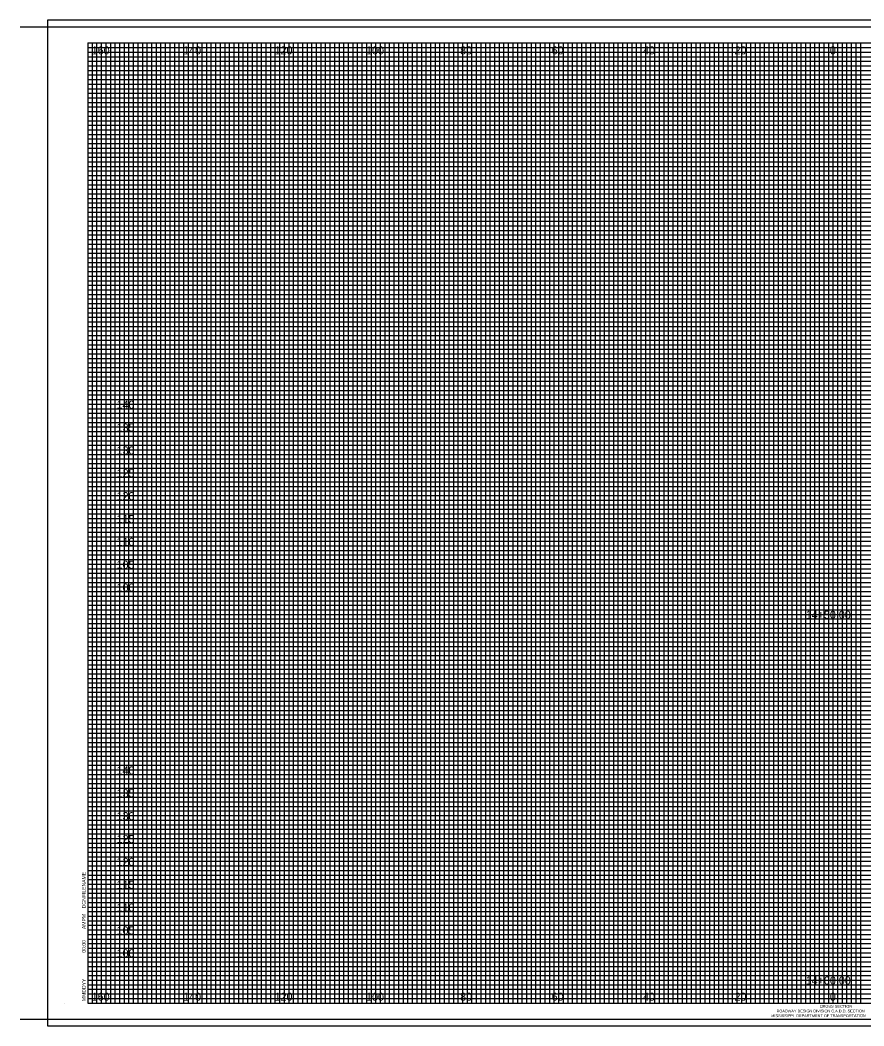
# Model space of a CAD drawing. Extents: x 21281 to 21817, y 6470 to 8300.
# Drawn here: x 21465 to 21649.5, y 7389.8 to 7609.8 of the extents above; entities that cross this region are included whole.
import ezdxf

# ---------------------------------------------------------------- set-up
doc = ezdxf.new("R2010")
doc.units = 0
for name, color, linetype in [('SHEET_BORDER', 7, 'Continuous'), ('SHEET_BORDER_TX', 7, 'Continuous'), ('SHEET_DATE_DGN_TX', 7, 'Continuous'), ('SHEET_PLOTTING_SHAPE', 7, 'Continuous'), ('XS_SHEET_LABELS_ELEVATION', 7, 'Continuous'), ('XS_SHEET_LABELS_OFFSET', 7, 'Continuous'), ('XS_SHEET_LABELS_STATION', 7, 'Continuous'), ('XS_SHEET_MAJOR_GRIDS', 7, 'Continuous'), ('XS_SHEET_MEDIUM_GRIDS', 7, 'Continuous'), ('XS_SHEET_MINOR_GRIDS', 7, 'Continuous')]:
    doc.layers.add(name, color=color, linetype=linetype)

msp = doc.modelspace()

# ---------------------------------------------------------------- linework, layer by layer
at = {"layer": 'SHEET_BORDER'}
for p, q in [((21465.04, 7608.34), (21817.04, 7608.34)), ((21479.84, 7604.84), (21814.84, 7604.84)), ((21479.84, 7604.84), (21479.84, 7394.84)), ((21623.84, 7394.84), (21623.84, 7604.84)), ((21474.84, 7394.84), (21474.84, 7394.84)), ((21479.84, 7394.84), (21814.84, 7394.84)), ((21465.04, 7391.34), (21817.04, 7391.34))]:
    msp.add_line(p, q, dxfattribs=at)
at = {"layer": 'SHEET_PLOTTING_SHAPE'}
msp.add_lwpolyline([(21471.04, 7389.84), (21817.04, 7389.84), (21817.04, 7609.84), (21471.04, 7609.84)], close=True, dxfattribs=at)
at = {"layer": 'XS_SHEET_MAJOR_GRIDS'}
for p, q in [((21484.84, 7394.84), (21484.84, 7604.84)), ((21494.84, 7394.84), (21494.84, 7604.84)), ((21504.84, 7394.84), (21504.84, 7604.84)), ((21514.84, 7394.84), (21514.84, 7604.84)), ((21524.84, 7394.84), (21524.84, 7604.84)), ((21534.84, 7394.84), (21534.84, 7604.84)), ((21544.84, 7394.84), (21544.84, 7604.84)), ((21554.84, 7394.84), (21554.84, 7604.84)), ((21564.84, 7394.84), (21564.84, 7604.84)), ((21574.84, 7394.84), (21574.84, 7604.84)), ((21584.84, 7394.84), (21584.84, 7604.84)), ((21594.84, 7394.84), (21594.84, 7604.84)), ((21604.84, 7394.84), (21604.84, 7604.84)), ((21614.84, 7394.84), (21614.84, 7604.84)), ((21624.84, 7394.84), (21624.84, 7604.84)), ((21634.84, 7394.84), (21634.84, 7604.84)), ((21644.84, 7394.84), (21644.84, 7604.84)), ((21479.84, 7594.84), (21814.84, 7594.84)), ((21479.84, 7584.84), (21814.84, 7584.84)), ((21479.84, 7574.84), (21814.84, 7574.84)), ((21479.84, 7564.84), (21814.84, 7564.84)), ((21479.84, 7554.84), (21814.84, 7554.84)), ((21479.84, 7544.84), (21814.84, 7544.84)), ((21479.84, 7534.84), (21814.84, 7534.84)), ((21479.84, 7524.84), (21814.84, 7524.84)), ((21479.84, 7514.84), (21814.84, 7514.84)), ((21479.84, 7504.84), (21814.84, 7504.84)), ((21479.84, 7494.84), (21814.84, 7494.84)), ((21479.84, 7484.84), (21814.84, 7484.84)), ((21479.84, 7474.84), (21814.84, 7474.84)), ((21479.84, 7464.84), (21814.84, 7464.84)), ((21479.84, 7454.84), (21814.84, 7454.84)), ((21479.84, 7444.84), (21814.84, 7444.84)), ((21479.84, 7434.84), (21814.84, 7434.84)), ((21479.84, 7424.84), (21814.84, 7424.84)), ((21479.84, 7414.84), (21814.84, 7414.84)), ((21479.84, 7404.84), (21814.84, 7404.84))]:
    msp.add_line(p, q, dxfattribs=at)
at = {"layer": 'XS_SHEET_MEDIUM_GRIDS'}
for p, q in [((21489.84, 7394.84), (21489.84, 7604.84)), ((21499.84, 7394.84), (21499.84, 7604.84)), ((21509.84, 7394.84), (21509.84, 7604.84)), ((21519.84, 7394.84), (21519.84, 7604.84)), ((21529.84, 7394.84), (21529.84, 7604.84)), ((21539.84, 7394.84), (21539.84, 7604.84)), ((21549.84, 7394.84), (21549.84, 7604.84)), ((21559.84, 7394.84), (21559.84, 7604.84)), ((21569.84, 7394.84), (21569.84, 7604.84)), ((21579.84, 7394.84), (21579.84, 7604.84)), ((21589.84, 7394.84), (21589.84, 7604.84)), ((21599.84, 7394.84), (21599.84, 7604.84)), ((21609.84, 7394.84), (21609.84, 7604.84)), ((21619.84, 7394.84), (21619.84, 7604.84)), ((21629.84, 7394.84), (21629.84, 7604.84)), ((21639.84, 7394.84), (21639.84, 7604.84)), ((21479.84, 7599.84), (21787.84, 7599.84)), ((21479.84, 7589.84), (21814.84, 7589.84)), ((21479.84, 7579.84), (21814.84, 7579.84)), ((21479.84, 7569.84), (21814.84, 7569.84)), ((21479.84, 7559.84), (21814.84, 7559.84)), ((21479.84, 7549.84), (21814.84, 7549.84)), ((21479.84, 7539.84), (21814.84, 7539.84)), ((21479.84, 7529.84), (21814.84, 7529.84)), ((21479.84, 7519.84), (21814.84, 7519.84)), ((21479.84, 7509.84), (21814.84, 7509.84)), ((21479.84, 7499.84), (21814.84, 7499.84)), ((21479.84, 7489.84), (21814.84, 7489.84)), ((21479.84, 7479.84), (21814.84, 7479.84)), ((21479.84, 7469.84), (21814.84, 7469.84)), ((21479.84, 7459.84), (21814.84, 7459.84)), ((21479.84, 7449.84), (21814.84, 7449.84)), ((21479.84, 7439.84), (21814.84, 7439.84)), ((21479.84, 7429.84), (21814.84, 7429.84)), ((21479.84, 7419.84), (21814.84, 7419.84)), ((21479.84, 7409.84), (21814.84, 7409.84)), ((21479.84, 7399.84), (21804.84, 7399.84))]:
    msp.add_line(p, q, dxfattribs=at)
at = {"layer": 'XS_SHEET_MINOR_GRIDS'}
for p, q in [((21479.84, 7603.84), (21787.84, 7603.84)), ((21480.84, 7394.84), (21480.84, 7604.84)), ((21481.84, 7394.84), (21481.84, 7604.84)), ((21482.84, 7394.84), (21482.84, 7604.84)), ((21483.84, 7394.84), (21483.84, 7604.84)), ((21485.84, 7394.84), (21485.84, 7604.84)), ((21486.84, 7394.84), (21486.84, 7604.84)), ((21487.84, 7394.84), (21487.84, 7604.84)), ((21488.84, 7394.84), (21488.84, 7604.84)), ((21490.84, 7394.84), (21490.84, 7604.84)), ((21491.84, 7394.84), (21491.84, 7604.84)), ((21492.84, 7394.84), (21492.84, 7604.84)), ((21493.84, 7394.84), (21493.84, 7604.84)), ((21495.84, 7394.84), (21495.84, 7604.84)), ((21496.84, 7394.84), (21496.84, 7604.84)), ((21497.84, 7394.84), (21497.84, 7604.84)), ((21498.84, 7394.84), (21498.84, 7604.84)), ((21500.84, 7394.84), (21500.84, 7604.84)), ((21501.84, 7394.84), (21501.84, 7604.84)), ((21502.84, 7394.84), (21502.84, 7604.84)), ((21503.84, 7394.84), (21503.84, 7604.84)), ((21505.84, 7394.84), (21505.84, 7604.84)), ((21506.84, 7394.84), (21506.84, 7604.84)), ((21507.84, 7394.84), (21507.84, 7604.84)), ((21508.84, 7394.84), (21508.84, 7604.84)), ((21510.84, 7394.84), (21510.84, 7604.84)), ((21511.84, 7394.84), (21511.84, 7604.84)), ((21512.84, 7394.84), (21512.84, 7604.84)), ((21513.84, 7394.84), (21513.84, 7604.84)), ((21515.84, 7394.84), (21515.84, 7604.84)), ((21516.84, 7394.84), (21516.84, 7604.84)), ((21517.84, 7394.84), (21517.84, 7604.84)), ((21518.84, 7394.84), (21518.84, 7604.84)), ((21520.84, 7394.84), (21520.84, 7604.84)), ((21521.84, 7394.84), (21521.84, 7604.84)), ((21522.84, 7394.84), (21522.84, 7604.84)), ((21523.84, 7394.84), (21523.84, 7604.84)), ((21525.84, 7394.84), (21525.84, 7604.84)), ((21526.84, 7394.84), (21526.84, 7604.84)), ((21527.84, 7394.84), (21527.84, 7604.84)), ((21528.84, 7394.84), (21528.84, 7604.84)), ((21530.84, 7394.84), (21530.84, 7604.84)), ((21531.84, 7394.84), (21531.84, 7604.84)), ((21532.84, 7394.84), (21532.84, 7604.84)), ((21533.84, 7394.84), (21533.84, 7604.84)), ((21535.84, 7394.84), (21535.84, 7604.84)), ((21536.84, 7394.84), (21536.84, 7604.84)), ((21537.84, 7394.84), (21537.84, 7604.84)), ((21538.84, 7394.84), (21538.84, 7604.84)), ((21540.84, 7394.84), (21540.84, 7604.84)), ((21541.84, 7394.84), (21541.84, 7604.84)), ((21542.84, 7394.84), (21542.84, 7604.84)), ((21543.84, 7394.84), (21543.84, 7604.84)), ((21545.84, 7394.84), (21545.84, 7604.84)), ((21546.84, 7394.84), (21546.84, 7604.84)), ((21547.84, 7394.84), (21547.84, 7604.84)), ((21548.84, 7394.84), (21548.84, 7604.84)), ((21550.84, 7394.84), (21550.84, 7604.84)), ((21551.84, 7394.84), (21551.84, 7604.84)), ((21552.84, 7394.84), (21552.84, 7604.84)), ((21553.84, 7394.84), (21553.84, 7604.84)), ((21555.84, 7394.84), (21555.84, 7604.84)), ((21556.84, 7394.84), (21556.84, 7604.84)), ((21557.84, 7394.84), (21557.84, 7604.84)), ((21558.84, 7394.84), (21558.84, 7604.84)), ((21560.84, 7394.84), (21560.84, 7604.84)), ((21561.84, 7394.84), (21561.84, 7604.84)), ((21562.84, 7394.84), (21562.84, 7604.84)), ((21563.84, 7394.84), (21563.84, 7604.84)), ((21565.84, 7394.84), (21565.84, 7604.84)), ((21566.84, 7394.84), (21566.84, 7604.84)), ((21567.84, 7394.84), (21567.84, 7604.84)), ((21568.84, 7394.84), (21568.84, 7604.84)), ((21570.84, 7394.84), (21570.84, 7604.84)), ((21571.84, 7394.84), (21571.84, 7604.84)), ((21572.84, 7394.84), (21572.84, 7604.84)), ((21573.84, 7394.84), (21573.84, 7604.84)), ((21575.84, 7394.84), (21575.84, 7604.84)), ((21576.84, 7394.84), (21576.84, 7604.84)), ((21577.84, 7394.84), (21577.84, 7604.84)), ((21578.84, 7394.84), (21578.84, 7604.84)), ((21580.84, 7394.84), (21580.84, 7604.84)), ((21581.84, 7394.84), (21581.84, 7604.84)), ((21582.84, 7394.84), (21582.84, 7604.84)), ((21583.84, 7394.84), (21583.84, 7604.84)), ((21585.84, 7394.84), (21585.84, 7604.84)), ((21586.84, 7394.84), (21586.84, 7604.84)), ((21587.84, 7394.84), (21587.84, 7604.84)), ((21588.84, 7394.84), (21588.84, 7604.84)), ((21590.84, 7394.84), (21590.84, 7604.84)), ((21591.84, 7394.84), (21591.84, 7604.84)), ((21592.84, 7394.84), (21592.84, 7604.84)), ((21593.84, 7394.84), (21593.84, 7604.84)), ((21595.84, 7394.84), (21595.84, 7604.84)), ((21596.84, 7394.84), (21596.84, 7604.84)), ((21597.84, 7394.84), (21597.84, 7604.84)), ((21598.84, 7394.84), (21598.84, 7604.84)), ((21600.84, 7394.84), (21600.84, 7604.84)), ((21601.84, 7394.84), (21601.84, 7604.84)), ((21602.84, 7394.84), (21602.84, 7604.84)), ((21603.84, 7394.84), (21603.84, 7604.84)), ((21605.84, 7394.84), (21605.84, 7604.84)), ((21606.84, 7394.84), (21606.84, 7604.84)), ((21607.84, 7394.84), (21607.84, 7604.84)), ((21608.84, 7394.84), (21608.84, 7604.84)), ((21610.84, 7394.84), (21610.84, 7604.84)), ((21611.84, 7394.84), (21611.84, 7604.84)), ((21612.84, 7394.84), (21612.84, 7604.84)), ((21613.84, 7394.84), (21613.84, 7604.84)), ((21615.84, 7394.84), (21615.84, 7604.84)), ((21616.84, 7394.84), (21616.84, 7604.84)), ((21617.84, 7394.84), (21617.84, 7604.84)), ((21618.84, 7394.84), (21618.84, 7604.84)), ((21620.84, 7394.84), (21620.84, 7604.84)), ((21621.84, 7394.84), (21621.84, 7604.84)), ((21622.84, 7394.84), (21622.84, 7604.84)), ((21625.84, 7394.84), (21625.84, 7604.84)), ((21626.84, 7394.84), (21626.84, 7604.84)), ((21627.84, 7394.84), (21627.84, 7604.84)), ((21628.84, 7394.84), (21628.84, 7604.84)), ((21630.84, 7394.84), (21630.84, 7604.84)), ((21631.84, 7394.84), (21631.84, 7604.84)), ((21632.84, 7394.84), (21632.84, 7604.84)), ((21633.84, 7394.84), (21633.84, 7604.84)), ((21635.84, 7394.84), (21635.84, 7604.84)), ((21636.84, 7394.84), (21636.84, 7604.84)), ((21637.84, 7394.84), (21637.84, 7604.84)), ((21638.84, 7394.84), (21638.84, 7604.84)), ((21640.84, 7394.84), (21640.84, 7604.84)), ((21641.84, 7394.84), (21641.84, 7604.84)), ((21642.84, 7394.84), (21642.84, 7604.84)), ((21643.84, 7394.84), (21643.84, 7604.84)), ((21645.84, 7394.84), (21645.84, 7604.84)), ((21646.84, 7394.84), (21646.84, 7604.84)), ((21647.84, 7394.84), (21647.84, 7604.84)), ((21648.84, 7394.84), (21648.84, 7604.84)), ((21479.84, 7602.84), (21787.84, 7602.84)), ((21479.84, 7601.84), (21787.84, 7601.84)), ((21479.84, 7600.84), (21787.84, 7600.84)), ((21479.84, 7598.84), (21787.84, 7598.84)), ((21479.84, 7597.84), (21787.84, 7597.84)), ((21479.84, 7596.84), (21787.84, 7596.84)), ((21479.84, 7595.84), (21814.84, 7595.84)), ((21479.84, 7593.84), (21814.84, 7593.84)), ((21479.84, 7592.84), (21814.84, 7592.84)), ((21479.84, 7591.84), (21814.84, 7591.84)), ((21479.84, 7590.84), (21814.84, 7590.84)), ((21479.84, 7588.84), (21814.84, 7588.84)), ((21479.84, 7587.84), (21814.84, 7587.84)), ((21479.84, 7586.84), (21814.84, 7586.84)), ((21479.84, 7585.84), (21814.84, 7585.84)), ((21479.84, 7583.84), (21814.84, 7583.84)), ((21479.84, 7582.84), (21814.84, 7582.84)), ((21479.84, 7581.84), (21814.84, 7581.84)), ((21479.84, 7580.84), (21814.84, 7580.84)), ((21479.84, 7578.84), (21814.84, 7578.84)), ((21479.84, 7577.84), (21814.84, 7577.84)), ((21479.84, 7576.84), (21814.84, 7576.84)), ((21479.84, 7575.84), (21814.84, 7575.84)), ((21479.84, 7573.84), (21814.84, 7573.84)), ((21479.84, 7572.84), (21814.84, 7572.84)), ((21479.84, 7571.84), (21814.84, 7571.84)), ((21479.84, 7570.84), (21814.84, 7570.84)), ((21479.84, 7568.84), (21814.84, 7568.84)), ((21479.84, 7567.84), (21814.84, 7567.84)), ((21479.84, 7566.84), (21814.84, 7566.84)), ((21479.84, 7565.84), (21814.84, 7565.84)), ((21479.84, 7563.84), (21814.84, 7563.84)), ((21479.84, 7562.84), (21814.84, 7562.84)), ((21479.84, 7561.84), (21814.84, 7561.84)), ((21479.84, 7560.84), (21814.84, 7560.84)), ((21479.84, 7558.84), (21814.84, 7558.84)), ((21479.84, 7557.84), (21814.84, 7557.84)), ((21479.84, 7556.84), (21814.84, 7556.84)), ((21479.84, 7555.84), (21814.84, 7555.84)), ((21479.84, 7553.84), (21814.84, 7553.84)), ((21479.84, 7552.84), (21814.84, 7552.84)), ((21479.84, 7551.84), (21814.84, 7551.84)), ((21479.84, 7550.84), (21814.84, 7550.84)), ((21479.84, 7548.84), (21814.84, 7548.84)), ((21479.84, 7547.84), (21814.84, 7547.84)), ((21479.84, 7546.84), (21814.84, 7546.84)), ((21479.84, 7545.84), (21814.84, 7545.84)), ((21479.84, 7543.84), (21814.84, 7543.84)), ((21479.84, 7542.84), (21814.84, 7542.84)), ((21479.84, 7541.84), (21814.84, 7541.84)), ((21479.84, 7540.84), (21814.84, 7540.84)), ((21479.84, 7538.84), (21814.84, 7538.84)), ((21479.84, 7537.84), (21814.84, 7537.84)), ((21479.84, 7536.84), (21814.84, 7536.84)), ((21479.84, 7535.84), (21814.84, 7535.84)), ((21479.84, 7533.84), (21814.84, 7533.84)), ((21479.84, 7532.84), (21814.84, 7532.84)), ((21479.84, 7531.84), (21814.84, 7531.84)), ((21479.84, 7530.84), (21814.84, 7530.84)), ((21479.84, 7528.84), (21814.84, 7528.84)), ((21479.84, 7527.84), (21814.84, 7527.84)), ((21479.84, 7526.84), (21814.84, 7526.84)), ((21479.84, 7525.84), (21814.84, 7525.84)), ((21479.84, 7523.84), (21814.84, 7523.84)), ((21479.84, 7522.84), (21814.84, 7522.84)), ((21479.84, 7521.84), (21814.84, 7521.84)), ((21479.84, 7520.84), (21814.84, 7520.84)), ((21479.84, 7518.84), (21814.84, 7518.84)), ((21479.84, 7517.84), (21814.84, 7517.84)), ((21479.84, 7516.84), (21814.84, 7516.84)), ((21479.84, 7515.84), (21814.84, 7515.84)), ((21479.84, 7513.84), (21814.84, 7513.84)), ((21479.84, 7512.84), (21814.84, 7512.84)), ((21479.84, 7511.84), (21814.84, 7511.84)), ((21479.84, 7510.84), (21814.84, 7510.84)), ((21479.84, 7508.84), (21814.84, 7508.84)), ((21479.84, 7507.84), (21814.84, 7507.84)), ((21479.84, 7506.84), (21814.84, 7506.84)), ((21479.84, 7505.84), (21814.84, 7505.84)), ((21479.84, 7503.84), (21814.84, 7503.84)), ((21479.84, 7502.84), (21814.84, 7502.84)), ((21479.84, 7501.84), (21814.84, 7501.84)), ((21479.84, 7500.84), (21814.84, 7500.84)), ((21479.84, 7498.84), (21814.84, 7498.84)), ((21479.84, 7497.84), (21814.84, 7497.84)), ((21479.84, 7496.84), (21814.84, 7496.84)), ((21479.84, 7495.84), (21814.84, 7495.84)), ((21479.84, 7493.84), (21814.84, 7493.84)), ((21479.84, 7492.84), (21814.84, 7492.84)), ((21479.84, 7491.84), (21814.84, 7491.84)), ((21479.84, 7490.84), (21814.84, 7490.84)), ((21479.84, 7488.84), (21814.84, 7488.84)), ((21479.84, 7487.84), (21814.84, 7487.84)), ((21479.84, 7486.84), (21814.84, 7486.84)), ((21479.84, 7485.84), (21814.84, 7485.84)), ((21479.84, 7483.84), (21814.84, 7483.84)), ((21479.84, 7482.84), (21814.84, 7482.84)), ((21479.84, 7481.84), (21814.84, 7481.84)), ((21479.84, 7480.84), (21814.84, 7480.84)), ((21479.84, 7478.84), (21814.84, 7478.84)), ((21479.84, 7477.84), (21814.84, 7477.84)), ((21479.84, 7476.84), (21814.84, 7476.84)), ((21479.84, 7475.84), (21814.84, 7475.84)), ((21479.84, 7473.84), (21814.84, 7473.84)), ((21479.84, 7472.84), (21814.84, 7472.84)), ((21479.84, 7471.84), (21814.84, 7471.84)), ((21479.84, 7470.84), (21814.84, 7470.84)), ((21479.84, 7468.84), (21814.84, 7468.84)), ((21479.84, 7467.84), (21814.84, 7467.84)), ((21479.84, 7466.84), (21814.84, 7466.84)), ((21479.84, 7465.84), (21814.84, 7465.84)), ((21479.84, 7463.84), (21814.84, 7463.84)), ((21479.84, 7462.84), (21814.84, 7462.84)), ((21479.84, 7461.84), (21814.84, 7461.84)), ((21479.84, 7460.84), (21814.84, 7460.84)), ((21479.84, 7458.84), (21814.84, 7458.84)), ((21479.84, 7457.84), (21814.84, 7457.84)), ((21479.84, 7456.84), (21814.84, 7456.84)), ((21479.84, 7455.84), (21814.84, 7455.84)), ((21479.84, 7453.84), (21814.84, 7453.84)), ((21479.84, 7452.84), (21814.84, 7452.84)), ((21479.84, 7451.84), (21814.84, 7451.84)), ((21479.84, 7450.84), (21814.84, 7450.84)), ((21479.84, 7448.84), (21814.84, 7448.84)), ((21479.84, 7447.84), (21814.84, 7447.84)), ((21479.84, 7446.84), (21814.84, 7446.84)), ((21479.84, 7445.84), (21814.84, 7445.84)), ((21479.84, 7443.84), (21814.84, 7443.84)), ((21479.84, 7442.84), (21814.84, 7442.84)), ((21479.84, 7441.84), (21814.84, 7441.84)), ((21479.84, 7440.84), (21814.84, 7440.84)), ((21479.84, 7438.84), (21814.84, 7438.84)), ((21479.84, 7437.84), (21814.84, 7437.84)), ((21479.84, 7436.84), (21814.84, 7436.84)), ((21479.84, 7435.84), (21814.84, 7435.84)), ((21479.84, 7433.84), (21814.84, 7433.84)), ((21479.84, 7432.84), (21814.84, 7432.84)), ((21479.84, 7431.84), (21814.84, 7431.84)), ((21479.84, 7430.84), (21814.84, 7430.84)), ((21479.84, 7428.84), (21814.84, 7428.84)), ((21479.84, 7427.84), (21814.84, 7427.84)), ((21479.84, 7426.84), (21814.84, 7426.84)), ((21479.84, 7425.84), (21814.84, 7425.84)), ((21479.84, 7423.84), (21814.84, 7423.84)), ((21479.84, 7422.84), (21814.84, 7422.84)), ((21479.84, 7421.84), (21814.84, 7421.84)), ((21479.84, 7420.84), (21814.84, 7420.84)), ((21479.84, 7418.84), (21814.84, 7418.84)), ((21479.84, 7417.84), (21814.84, 7417.84)), ((21479.84, 7416.84), (21814.84, 7416.84)), ((21479.84, 7415.84), (21814.84, 7415.84)), ((21479.84, 7415.84), (21814.84, 7415.84)), ((21479.84, 7415.84), (21814.84, 7415.84)), ((21479.84, 7413.84), (21814.84, 7413.84)), ((21479.84, 7412.84), (21814.84, 7412.84)), ((21479.84, 7411.84), (21814.84, 7411.84)), ((21479.84, 7410.84), (21814.84, 7410.84)), ((21479.84, 7408.84), (21814.84, 7408.84)), ((21479.84, 7407.84), (21814.84, 7407.84)), ((21479.84, 7406.84), (21814.84, 7406.84)), ((21479.84, 7405.84), (21814.84, 7405.84)), ((21479.84, 7403.84), (21804.84, 7403.84)), ((21479.84, 7402.84), (21804.84, 7402.84)), ((21479.84, 7401.84), (21804.84, 7401.84)), ((21479.84, 7400.84), (21804.84, 7400.84)), ((21479.84, 7400.84), (21804.84, 7400.84)), ((21479.84, 7400.84), (21804.84, 7400.84)), ((21479.84, 7398.84), (21804.84, 7398.84)), ((21479.84, 7397.84), (21804.84, 7397.84)), ((21479.84, 7396.84), (21804.84, 7396.84)), ((21479.84, 7395.84), (21804.84, 7395.84))]:
    msp.add_line(p, q, dxfattribs=at)

# ---------------------------------------------------------------- texts
at = {"layer": 'SHEET_BORDER_TX'}
for s, height, p in [('CROSS SECTION', 0.62, (21639.87, 7393.81)), ('MISSISSIPPI  DEPARTMENT OF TRANSPORTATION', 0.61, (21629.27, 7391.75)), ('ROADWAY DESIGN DIVISION C.A.D.D. SECTION', 0.61, (21630.44, 7392.78))]:
    msp.add_text(s, height=height, dxfattribs=at).set_placement(p)
at = {"layer": 'SHEET_DATE_DGN_TX'}
for s, p in [('DGNFILENAME', (21479.37, 7415.54)), ('AMPM', (21479.37, 7411.02)), ('00:00', (21479.37, 7405.84)), ('MMDDYY', (21479.37, 7395.26))]:
    msp.add_text(s, height=0.8, rotation=90, dxfattribs=at).set_placement(p)
at = {"layer": 'XS_SHEET_LABELS_ELEVATION'}
for s, p in [('  140  ', (21484.84, 7524.84)), ('  135  ', (21484.84, 7519.84)), ('  130  ', (21484.84, 7514.84)), ('  125  ', (21484.84, 7509.84)), ('  120  ', (21484.84, 7504.84)), ('  115  ', (21484.84, 7499.84)), ('  110  ', (21484.84, 7494.84)), ('  105  ', (21484.84, 7489.84)), ('  100  ', (21484.84, 7484.84)), ('  140  ', (21484.84, 7444.84)), ('  135  ', (21484.84, 7439.84)), ('  130  ', (21484.84, 7434.84)), ('  125  ', (21484.84, 7429.84)), ('  120  ', (21484.84, 7424.84)), ('  115  ', (21484.84, 7419.84)), ('  110  ', (21484.84, 7414.84)), ('  105  ', (21484.84, 7409.84)), ('  100  ', (21484.84, 7404.84))]:
    msp.add_text(s, height=1.75, dxfattribs=at).set_placement(p)
at = {"layer": 'XS_SHEET_LABELS_OFFSET'}
for s, p in [('  160  ', (21479.4, 7602.34)), ('  140  ', (21499.39, 7602.34)), ('  120  ', (21519.39, 7602.34)), ('  100  ', (21539.39, 7602.34)), ('  80  ', (21559.95, 7602.34)), ('  60  ', (21579.97, 7602.34)), ('  40  ', (21599.95, 7602.34)), ('  20  ', (21619.95, 7602.34)), ('  0  ', (21640.81, 7602.34)), ('  0  ', (21640.81, 7602.34)), ('  160  ', (21479.4, 7395.34)), ('  140  ', (21499.39, 7395.34)), ('  120  ', (21519.39, 7395.34)), ('  100  ', (21539.39, 7395.34)), ('  80  ', (21559.95, 7395.34)), ('  60  ', (21579.97, 7395.34)), ('  40  ', (21599.95, 7395.34)), ('  20  ', (21619.95, 7395.34)), ('  0  ', (21640.81, 7395.34)), ('  0  ', (21640.81, 7395.34))]:
    msp.add_text(s, height=1.75, dxfattribs=at).set_placement(p)
at = {"layer": 'XS_SHEET_LABELS_STATION'}
for s, p in [('  14+50.00  ', (21635.54, 7478.89)), ('  14+00.00  ', (21635.54, 7398.89))]:
    msp.add_text(s, height=1.75, dxfattribs=at).set_placement(p)

doc.saveas('drawing.dxf')
